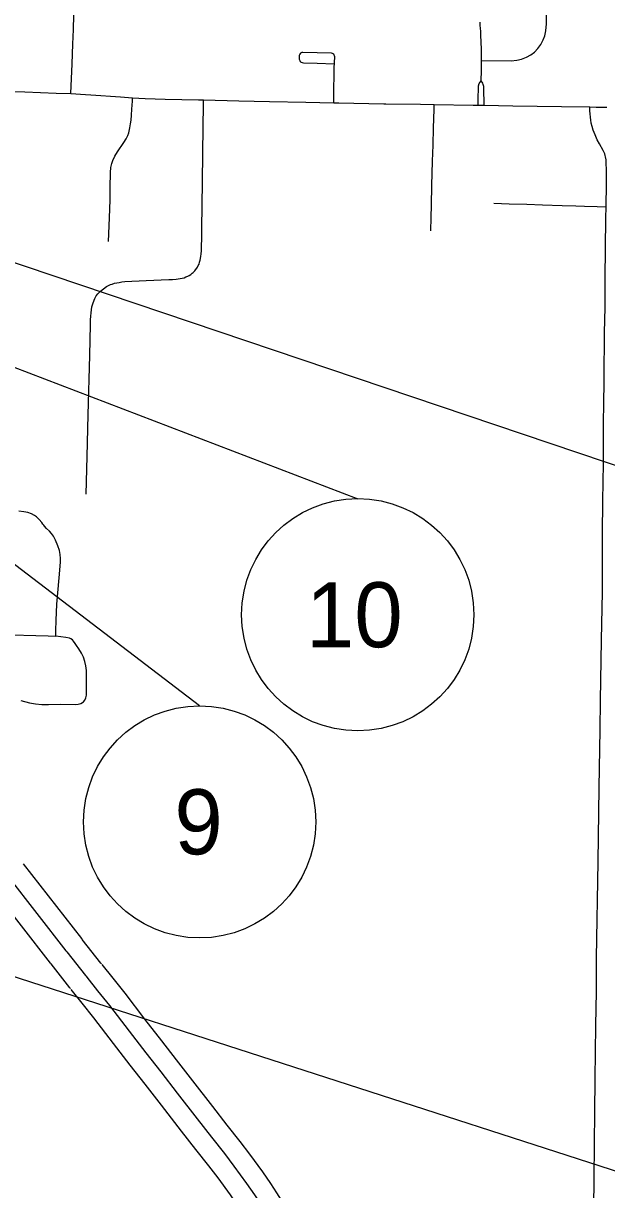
# Model space of a CAD drawing. Extents: x 1341221 to 1914484, y 79347 to 658398.
# Drawn here: x 1393794 to 1399525, y 603681 to 615143 of the extents above; entities that cross this region are included whole.
import ezdxf

# ---------------------------------------------------------------- set-up
doc = ezdxf.new("R2010")
doc.units = 0
for name, color, linetype in [('GM_X_County', 7, 'Continuous'), ('GM_X_County_Road_Text', 7, 'Continuous'), ('GM_X_State_Location', 7, 'Continuous'), ('GM_X_State_Shield', 7, 'Continuous'), ('GM_X_Unincorporated', 7, 'Continuous'), ('GM_X_US_Shield', 7, 'Continuous')]:
    doc.layers.add(name, color=color, linetype=linetype)

msp = doc.modelspace()

# ---------------------------------------------------------------- linework, layer by layer
at = {"layer": 'GM_X_County'}
for p, q in [((1395526, 608436), (1388625, 613703)), ((1390836, 606703), (1399981, 603745))]:
    msp.add_line(p, q, dxfattribs=at)
for points in [[(1394373, 606140), (1394367, 606148), (1393794, 606882)], [(1394067, 605899), (1394060, 605907), (1393486, 606642)], [(1394562, 605900), (1394556, 605907), (1394373, 606140)], [(1394258, 605656), (1394251, 605664), (1394067, 605899)], [(1396950, 602405), (1396789, 602722), (1396650, 602997), (1396539, 603209), (1396446, 603383), (1396352, 603543), (1396285, 603651), (1396226, 603741), (1396147, 603855), (1396020, 604029), (1395924, 604154), (1395797, 604316), (1395655, 604497), (1395459, 604749), (1395299, 604957), (1395153, 605144), (1394989, 605356), (1394794, 605611), (1394677, 605758), (1394568, 605892)], [(1396603, 602228), (1396441, 602546), (1396303, 602819), (1396195, 603027), (1396106, 603192), (1396018, 603341), (1395957, 603441), (1395903, 603522), (1395829, 603629), (1395707, 603796), (1395616, 603915), (1395490, 604075), (1395347, 604257), (1395151, 604511), (1394991, 604718), (1394845, 604905), (1394680, 605118), (1394487, 605371), (1394372, 605514), (1394265, 605648)]]:
    msp.add_lwpolyline(points, dxfattribs=at)
for centre in [(1397080, 609331), (1395526, 607295)]:
    msp.add_circle(centre, 1141, dxfattribs=at)
at = {"layer": 'GM_X_County_Road_Text'}
for p, q in [((1388625, 613703), (1397080, 610471)), ((1392194, 613303), (1400482, 610504))]:
    msp.add_line(p, q, dxfattribs=at)
at = {"layer": 'GM_X_State_Location'}
msp.add_line((1394410, 605778), (1394417, 605770), dxfattribs=at)
for points in [[(1393640, 606762), (1394213, 606028), (1394220, 606019)], [(1394220, 606019), (1394404, 605786), (1394410, 605778)], [(1394417, 605770), (1394524, 605636), (1394640, 605491), (1394835, 605237), (1394999, 605024), (1395145, 604838), (1395305, 604630), (1395501, 604377), (1395643, 604196), (1395770, 604035), (1395863, 603913), (1395988, 603742), (1396065, 603631), (1396121, 603546), (1396185, 603442), (1396276, 603287), (1396367, 603118), (1396476, 602908), (1396615, 602634), (1396777, 602316)]]:
    msp.add_lwpolyline(points, dxfattribs=at)
at = {"layer": 'GM_X_State_Shield'}
for points in [[(1398296, 614779), (1398586, 614774), (1398642, 614780), (1398690, 614791), (1398737, 614809), (1398780, 614833), (1398815, 614860), (1398849, 614896), (1398879, 614936), (1398902, 614980), (1398918, 615021), (1398929, 615069), (1398935, 615138), (1398942, 615618), (1398940, 616142), (1398945, 616297), (1398945, 616316), (1398948, 616413), (1398950, 616504), (1398954, 616679), (1398954, 616735), (1398958, 616940), (1398960, 616979)], [(1398293, 614577), (1398294, 614678), (1398296, 614779), (1398295, 614835), (1398295, 614889), (1398293, 614956), (1398290, 615026), (1398288, 615064), (1398286, 615096), (1398284, 615123), (1398281, 615153)], [(1396843, 614361), (1396845, 614428), (1396848, 614703), (1396853, 614813), (1396852, 614822), (1396849, 614831), (1396844, 614839), (1396837, 614844), (1396830, 614847), (1396822, 614849), (1396541, 614857), (1396531, 614856), (1396524, 614853), (1396516, 614849), (1396510, 614841), (1396506, 614834), (1396504, 614826), (1396503, 614818), (1396503, 614810), (1396505, 614792), (1396509, 614777), (1396513, 614769), (1396518, 614764), (1396524, 614761), (1396534, 614758), (1396546, 614756), (1396681, 614751), (1396847, 614746)], [(1398263, 614339), (1398263, 614391), (1398264, 614440), (1398265, 614472), (1398265, 614503), (1398266, 614516), (1398267, 614529), (1398274, 614550), (1398281, 614564), (1398293, 614577)], [(1398322, 614338), (1398321, 614393), (1398320, 614450), (1398319, 614490), (1398319, 614505), (1398317, 614521), (1398315, 614532), (1398313, 614543), (1398308, 614556), (1398302, 614566), (1398293, 614577)], [(1394412, 610515), (1394421, 610885), (1394432, 611296), (1394447, 611878), (1394453, 612182), (1394454, 612230), (1394456, 612264), (1394459, 612299), (1394463, 612327), (1394468, 612355), (1394479, 612397), (1394496, 612437), (1394511, 612464), (1394526, 612484), (1394551, 612511), (1394580, 612535), (1394611, 612556), (1394649, 612575), (1394668, 612581), (1394691, 612588), (1394712, 612593), (1394734, 612597), (1394762, 612601), (1394790, 612604), (1395001, 612616), (1395225, 612624), (1395261, 612626), (1395296, 612629), (1395334, 612634), (1395355, 612638), (1395373, 612643), (1395391, 612650), (1395409, 612658), (1395424, 612666), (1395438, 612675), (1395453, 612686), (1395464, 612695), (1395478, 612709), (1395487, 612719), (1395499, 612735), (1395506, 612747), (1395512, 612762), (1395520, 612777), (1395526, 612794), (1395532, 612814), (1395536, 612833), (1395539, 612854), (1395542, 612875), (1395544, 612909), (1395546, 612958), (1395547, 613021), (1395548, 613140), (1395550, 613339), (1395553, 613597), (1395557, 613850), (1395561, 614137), (1395563, 614330), (1395564, 614390)], [(1394630, 612998), (1394640, 613231), (1394647, 613408), (1394647, 613529), (1394650, 613676), (1394655, 613727), (1394662, 613765), (1394672, 613795), (1394693, 613836), (1394719, 613879), (1394782, 613972), (1394804, 614006), (1394819, 614039), (1394829, 614066), (1394840, 614116), (1394848, 614156), (1394853, 614192), (1394857, 614241), (1394860, 614299), (1394865, 614377), (1394868, 614411)], [(1397797, 613105), (1397801, 613233), (1397804, 613355), (1397809, 613550), (1397815, 613789), (1397820, 613945), (1397824, 614117), (1397829, 614295), (1397830, 614345)], [(1398418, 613374), (1398567, 613370), (1398742, 613365), (1398895, 613360), (1399087, 613354), (1399224, 613350), (1399309, 613347), (1399431, 613343), (1399520, 613340)]]:
    msp.add_lwpolyline(points, dxfattribs=at)
at = {"layer": 'GM_X_Unincorporated'}
for points in [[(1391397, 614551), (1391625, 614544), (1391735, 614540), (1392059, 614528), (1392166, 614525), (1392475, 614516), (1393063, 614492), (1393226, 614487), (1393536, 614476), (1393808, 614468), (1394116, 614458), (1394260, 614453), (1394406, 614443), (1394458, 614440)], [(1394458, 614440), (1394749, 614420), (1394868, 614411), (1394990, 614405), (1395188, 614399), (1395514, 614391), (1395564, 614390), (1395910, 614382), (1396211, 614375), (1396569, 614367), (1396843, 614361), (1396895, 614360), (1397336, 614352), (1397357, 614352)], [(1397357, 614352), (1397695, 614347), (1397830, 614345), (1398213, 614340), (1398263, 614339), (1398322, 614338), (1398603, 614333), (1399083, 614324), (1399360, 614321), (1399421, 614320), (1399527, 614318)]]:
    msp.add_lwpolyline(points, dxfattribs=at)
at = {"layer": 'GM_X_US_Shield'}
for points in [[(1394260, 614453), (1394272, 614746), (1394281, 614937), (1394287, 615082), (1394294, 615368)], [(1399496, 611359), (1399496, 611370), (1399501, 611654), (1399505, 612102), (1399509, 612352), (1399512, 612634), (1399518, 613229), (1399520, 613340), (1399523, 613566), (1399523, 613717), (1399522, 613756), (1399520, 613800), (1399515, 613830), (1399512, 613845), (1399507, 613859), (1399492, 613893), (1399454, 613959), (1399433, 613999), (1399411, 614047), (1399393, 614094), (1399382, 614128), (1399374, 614163), (1399369, 614194), (1399365, 614218), (1399362, 614255), (1399361, 614281), (1399360, 614321)], [(1399494, 611165), (1399495, 611267), (1399496, 611359)], [(1399473, 609081), (1399483, 609555), (1399484, 609843), (1399485, 610125), (1399489, 610451), (1399493, 610816), (1399493, 610963), (1399494, 611165)], [(1394410, 608527), (1394413, 608540), (1394416, 608578), (1394416, 608712), (1394414, 608783), (1394409, 608827), (1394399, 608871), (1394384, 608913), (1394365, 608954), (1394339, 608997), (1394316, 609028), (1394304, 609047), (1394287, 609072), (1394276, 609085), (1394262, 609094), (1394249, 609099), (1394211, 609106), (1394114, 609119), (1394113, 609177), (1394116, 609273), (1394123, 609433), (1394145, 609694), (1394160, 609847), (1394160, 609885), (1394156, 609923), (1394148, 609961), (1394132, 610009), (1394110, 610063), (1394090, 610102), (1394071, 610128), (1394050, 610152), (1394022, 610179), (1394001, 610202), (1393994, 610212), (1393986, 610222), (1393975, 610236), (1393951, 610266), (1393923, 610292), (1393902, 610307), (1393873, 610321), (1393837, 610334), (1393800, 610343), (1393749, 610349)], [(1393552, 609138), (1394038, 609122), (1394114, 609119)], [(1399424, 605958), (1399441, 606904), (1399453, 607632), (1399463, 608201), (1399465, 608488), (1399473, 609081)], [(1393769, 608487), (1393856, 608465), (1393913, 608456), (1393976, 608450), (1394040, 608450), (1394162, 608453), (1394303, 608449), (1394334, 608452), (1394359, 608459), (1394376, 608468), (1394386, 608476), (1394397, 608491), (1394408, 608515), (1394410, 608527)], [(1399379, 601167), (1399380, 601327), (1399386, 601916), (1399389, 602345), (1399392, 602671), (1399394, 602895), (1399396, 603247), (1399403, 603778), (1399405, 604137), (1399409, 604438), (1399414, 604770), (1399420, 605295), (1399425, 605628), (1399424, 605958)]]:
    msp.add_lwpolyline(points, dxfattribs=at)

# ---------------------------------------------------------------- texts
at = {"layer": 'GM_X_County'}
for s, height, p in [('10', 638.8, (1396571, 609011)), ('9', 639, (1395278, 606976))]:
    msp.add_text(s, height=height, dxfattribs=at).set_placement(p)

doc.saveas('drawing.dxf')
